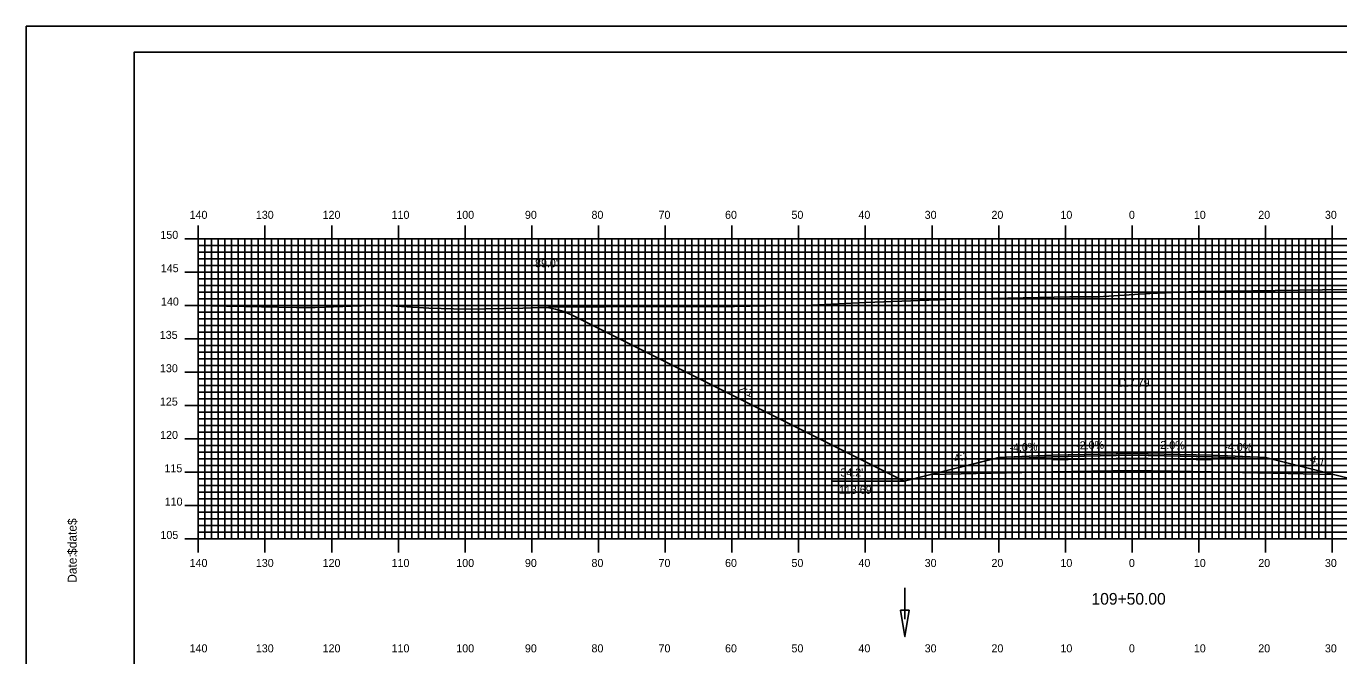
# Model space of a CAD drawing. Extents: x 1768874 to 1769217, y 442591 to 442811.
# Drawn here: x 1768874.2 to 1769071, y 442716.2 to 442810.5 of the extents above; entities that cross this region are included whole.
import ezdxf

# ---------------------------------------------------------------- set-up
doc = ezdxf.new("R2010")
doc.units = 0
for name, color, linetype in [('ANNOTATION', 7, 'Continuous'), ('BORDER', 7, 'Continuous'), ('D_Drainage_Ditch_Line', 7, 'Continuous'), ('D_Roadway_Centerline', 7, 'Continuous'), ('D_Roadway_Centerline_Text', 7, 'Continuous'), ('D_Roadway_Edge_Shoulder', 7, 'Continuous'), ('D_Roadway_Edge_TW', 7, 'Continuous'), ('D_Roadway_Pavement', 7, 'Continuous'), ('D_Roadway_SlopeLines', 7, 'Continuous'), ('D_Roadway_SubGrade', 7, 'Continuous'), ('D_Text_Standard', 7, 'Continuous'), ('H_V ANNOTATION', 7, 'Continuous'), ('MAJOR', 7, 'Continuous'), ('MINOR', 7, 'Continuous'), ('PDRAIN', 7, 'Continuous'), ('PLOT BOUNDARY', 7, 'Continuous'), ('S_Roadway_Centerline', 7, 'Continuous')]:
    doc.layers.add(name, color=color, linetype=linetype)

msp = doc.modelspace()

# ---------------------------------------------------------------- linework, layer by layer
at = {"layer": 'BORDER'}
msp.add_lwpolyline([(1768890.39, 442596.67), (1769210.39, 442596.67), (1769210.39, 442806.67), (1768890.39, 442806.67)], close=True, dxfattribs=at)
at = {"layer": 'D_Drainage_Ditch_Line'}
msp.add_line((1769005.93, 442721.66), (1769005.93, 442726.36), dxfattribs=at)
msp.add_lwpolyline([(1769006.58, 442722.97), (1769005.27, 442722.97), (1769005.93, 442719.03)], close=True, dxfattribs=at)
at = {"layer": 'D_Roadway_Centerline'}
msp.add_lwpolyline([(1768951.04, 442768.39), (1768952.29, 442768.36), (1768953.07, 442768.23), (1768953.54, 442768.15), (1768954.44, 442767.89), (1768954.79, 442767.78), (1768954.96, 442767.71), (1768956.04, 442767.24), (1769005.81, 442742.35), (1769005.81, 442742.35), (1769009.81, 442743.35), (1769009.82, 442743.35), (1769017.86, 442745.36), (1769019.99, 442745.9), (1769027.99, 442746.22), (1769030.45, 442746.27), (1769039.99, 442746.46), (1769051.99, 442746.22), (1769059.99, 442745.9), (1769070.16, 442743.35), (1769074.16, 442742.35)], dxfattribs=at)
at = {"layer": 'D_Roadway_Edge_Shoulder'}
for points in [[(1769027.99, 442746.22), (1769019.99, 442745.9), (1769019.99, 442745.65), (1769027.99, 442745.97)], [(1769051.99, 442746.22), (1769059.99, 442745.9), (1769059.99, 442745.65), (1769051.99, 442745.97)]]:
    msp.add_lwpolyline(points, close=True, dxfattribs=at)
at = {"layer": 'D_Roadway_Edge_TW'}
msp.add_lwpolyline([(1769027.99, 442745.97), (1769027.99, 442746.22), (1769039.99, 442746.46), (1769051.99, 442746.22), (1769051.99, 442745.97), (1769039.99, 442746.21)], close=True, dxfattribs=at)
at = {"layer": 'D_Roadway_Pavement'}
msp.add_lwpolyline([(1769027.99, 442745.55), (1769027.99, 442745.97), (1769039.99, 442746.21), (1769051.99, 442745.97), (1769051.99, 442745.55), (1769039.99, 442745.79)], close=True, dxfattribs=at)
at = {"layer": 'D_Roadway_SlopeLines'}
for points in [[(1769005.81, 442742.35), (1768956.04, 442767.24), (1768954.79, 442767.78), (1768953.54, 442768.15), (1768952.29, 442768.36), (1768951.04, 442768.39)], [(1769019.99, 442745.9), (1769005.81, 442742.35)], [(1769059.99, 442745.9), (1769074.16, 442742.35)]]:
    msp.add_lwpolyline(points, dxfattribs=at)
at = {"layer": 'D_Roadway_SubGrade'}
msp.add_lwpolyline([(1769027.99, 442743.72), (1769009.81, 442743.35), (1769019.99, 442745.9), (1769019.99, 442745.65), (1769027.99, 442745.97), (1769039.99, 442746.21), (1769051.99, 442745.97), (1769059.99, 442745.65), (1769059.99, 442745.9), (1769070.16, 442743.35), (1769051.99, 442743.72), (1769039.99, 442743.96)], close=True, dxfattribs=at)
at = {"layer": 'MAJOR'}
for p, q in [((1768899.99, 442780.67), (1768899.99, 442778.67)), ((1768909.99, 442780.67), (1768909.99, 442778.67)), ((1768919.99, 442780.67), (1768919.99, 442778.67)), ((1768929.99, 442780.67), (1768929.99, 442778.67)), ((1768939.99, 442780.67), (1768939.99, 442778.67)), ((1768949.99, 442780.67), (1768949.99, 442778.67)), ((1768959.99, 442780.67), (1768959.99, 442778.67)), ((1768969.99, 442780.67), (1768969.99, 442778.67)), ((1768979.99, 442780.67), (1768979.99, 442778.67)), ((1768989.99, 442780.67), (1768989.99, 442778.67)), ((1768999.99, 442780.67), (1768999.99, 442778.67)), ((1769009.99, 442780.67), (1769009.99, 442778.67)), ((1769019.99, 442780.67), (1769019.99, 442778.67)), ((1769029.99, 442780.67), (1769029.99, 442778.67)), ((1769039.99, 442780.67), (1769039.99, 442778.67)), ((1769049.99, 442780.67), (1769049.99, 442778.67)), ((1769059.99, 442780.67), (1769059.99, 442778.67)), ((1769069.99, 442780.67), (1769069.99, 442778.67)), ((1768897.98, 442778.67), (1768899.99, 442778.67)), ((1768899.99, 442778.67), (1769179.99, 442778.67)), ((1768899.99, 442733.67), (1768899.99, 442778.67)), ((1768899.99, 442733.67), (1768899.99, 442778.67)), ((1768899.99, 442778.67), (1769179.99, 442778.67)), ((1768909.99, 442733.67), (1768909.99, 442778.67)), ((1768919.99, 442733.67), (1768919.99, 442778.67)), ((1768929.99, 442733.67), (1768929.99, 442778.67)), ((1768939.99, 442733.67), (1768939.99, 442778.67)), ((1768949.99, 442733.67), (1768949.99, 442778.67)), ((1768959.99, 442733.67), (1768959.99, 442778.67)), ((1768969.99, 442733.67), (1768969.99, 442778.67)), ((1768979.99, 442733.67), (1768979.99, 442778.67)), ((1768989.99, 442733.67), (1768989.99, 442778.67)), ((1768999.99, 442733.67), (1768999.99, 442778.67)), ((1769009.99, 442733.67), (1769009.99, 442778.67)), ((1769019.99, 442733.67), (1769019.99, 442778.67)), ((1769029.99, 442733.67), (1769029.99, 442778.67)), ((1769039.99, 442733.67), (1769039.99, 442778.67)), ((1769049.99, 442733.67), (1769049.99, 442778.67)), ((1769059.99, 442733.67), (1769059.99, 442778.67)), ((1769069.99, 442733.67), (1769069.99, 442778.67)), ((1768897.98, 442773.67), (1768899.99, 442773.67)), ((1768899.99, 442773.67), (1769179.99, 442773.67)), ((1768897.98, 442768.67), (1768899.99, 442768.67)), ((1768899.99, 442768.67), (1769179.99, 442768.67)), ((1768897.98, 442763.67), (1768899.99, 442763.67)), ((1768899.99, 442763.67), (1769179.99, 442763.67)), ((1768897.98, 442758.67), (1768899.99, 442758.67)), ((1768899.99, 442758.67), (1769179.99, 442758.67)), ((1768897.98, 442753.67), (1768899.99, 442753.67)), ((1768899.99, 442753.67), (1769179.99, 442753.67)), ((1768897.98, 442748.67), (1768899.99, 442748.67)), ((1768899.99, 442748.67), (1769179.99, 442748.67)), ((1768897.98, 442743.67), (1768899.99, 442743.67)), ((1768899.99, 442743.67), (1769179.99, 442743.67)), ((1768897.98, 442738.67), (1768899.99, 442738.67)), ((1768899.99, 442738.67), (1769179.99, 442738.67)), ((1768897.98, 442733.67), (1768899.99, 442733.67)), ((1768899.99, 442733.67), (1769179.99, 442733.67)), ((1768899.99, 442733.67), (1769179.99, 442733.67)), ((1768899.99, 442731.66), (1768899.99, 442733.67)), ((1768909.99, 442731.66), (1768909.99, 442733.67)), ((1768919.99, 442731.66), (1768919.99, 442733.67)), ((1768929.99, 442731.66), (1768929.99, 442733.67)), ((1768939.99, 442731.66), (1768939.99, 442733.67)), ((1768949.99, 442731.66), (1768949.99, 442733.67)), ((1768959.99, 442731.66), (1768959.99, 442733.67)), ((1768969.99, 442731.66), (1768969.99, 442733.67)), ((1768979.99, 442731.66), (1768979.99, 442733.67)), ((1768989.99, 442731.66), (1768989.99, 442733.67)), ((1768999.99, 442731.66), (1768999.99, 442733.67)), ((1769009.99, 442731.66), (1769009.99, 442733.67)), ((1769019.99, 442731.66), (1769019.99, 442733.67)), ((1769029.99, 442731.66), (1769029.99, 442733.67)), ((1769039.99, 442731.66), (1769039.99, 442733.67)), ((1769049.99, 442731.66), (1769049.99, 442733.67)), ((1769059.99, 442731.66), (1769059.99, 442733.67)), ((1769069.99, 442731.66), (1769069.99, 442733.67))]:
    msp.add_line(p, q, dxfattribs=at)
at = {"layer": 'MINOR'}
for p, q in [((1768900.99, 442733.67), (1768900.99, 442778.67)), ((1768901.99, 442733.67), (1768901.99, 442778.67)), ((1768902.99, 442733.67), (1768902.99, 442778.67)), ((1768903.99, 442733.67), (1768903.99, 442778.67)), ((1768904.99, 442733.67), (1768904.99, 442778.67)), ((1768905.99, 442733.67), (1768905.99, 442778.67)), ((1768906.99, 442733.67), (1768906.99, 442778.67)), ((1768907.99, 442733.67), (1768907.99, 442778.67)), ((1768908.99, 442733.67), (1768908.99, 442778.67)), ((1768910.99, 442733.67), (1768910.99, 442778.67)), ((1768911.99, 442733.67), (1768911.99, 442778.67)), ((1768912.99, 442733.67), (1768912.99, 442778.67)), ((1768913.99, 442733.67), (1768913.99, 442778.67)), ((1768914.99, 442733.67), (1768914.99, 442778.67)), ((1768915.99, 442733.67), (1768915.99, 442778.67)), ((1768916.99, 442733.67), (1768916.99, 442778.67)), ((1768917.99, 442733.67), (1768917.99, 442778.67)), ((1768918.99, 442733.67), (1768918.99, 442778.67)), ((1768920.99, 442733.67), (1768920.99, 442778.67)), ((1768921.99, 442733.67), (1768921.99, 442778.67)), ((1768922.99, 442733.67), (1768922.99, 442778.67)), ((1768923.99, 442733.67), (1768923.99, 442778.67)), ((1768924.99, 442733.67), (1768924.99, 442778.67)), ((1768925.99, 442733.67), (1768925.99, 442778.67)), ((1768926.99, 442733.67), (1768926.99, 442778.67)), ((1768927.99, 442733.67), (1768927.99, 442778.67)), ((1768928.99, 442733.67), (1768928.99, 442778.67)), ((1768930.99, 442733.67), (1768930.99, 442778.67)), ((1768931.99, 442733.67), (1768931.99, 442778.67)), ((1768932.99, 442733.67), (1768932.99, 442778.67)), ((1768933.99, 442733.67), (1768933.99, 442778.67)), ((1768934.99, 442733.67), (1768934.99, 442778.67)), ((1768935.99, 442733.67), (1768935.99, 442778.67)), ((1768936.99, 442733.67), (1768936.99, 442778.67)), ((1768937.99, 442733.67), (1768937.99, 442778.67)), ((1768938.99, 442733.67), (1768938.99, 442778.67)), ((1768940.99, 442733.67), (1768940.99, 442778.67)), ((1768941.99, 442733.67), (1768941.99, 442778.67)), ((1768942.99, 442733.67), (1768942.99, 442778.67)), ((1768943.99, 442733.67), (1768943.99, 442778.67)), ((1768944.99, 442733.67), (1768944.99, 442778.67)), ((1768945.99, 442733.67), (1768945.99, 442778.67)), ((1768946.99, 442733.67), (1768946.99, 442778.67)), ((1768947.99, 442733.67), (1768947.99, 442778.67)), ((1768948.99, 442733.67), (1768948.99, 442778.67)), ((1768950.99, 442733.67), (1768950.99, 442778.67)), ((1768951.99, 442733.67), (1768951.99, 442778.67)), ((1768952.99, 442733.67), (1768952.99, 442778.67)), ((1768953.99, 442733.67), (1768953.99, 442778.67)), ((1768954.99, 442733.67), (1768954.99, 442778.67)), ((1768955.99, 442733.67), (1768955.99, 442778.67)), ((1768956.99, 442733.67), (1768956.99, 442778.67)), ((1768957.99, 442733.67), (1768957.99, 442778.67)), ((1768958.99, 442733.67), (1768958.99, 442778.67)), ((1768960.99, 442733.67), (1768960.99, 442778.67)), ((1768961.99, 442733.67), (1768961.99, 442778.67)), ((1768962.99, 442733.67), (1768962.99, 442778.67)), ((1768963.99, 442733.67), (1768963.99, 442778.67)), ((1768964.99, 442733.67), (1768964.99, 442778.67)), ((1768965.99, 442733.67), (1768965.99, 442778.67)), ((1768966.99, 442733.67), (1768966.99, 442778.67)), ((1768967.99, 442733.67), (1768967.99, 442778.67)), ((1768968.99, 442733.67), (1768968.99, 442778.67)), ((1768970.99, 442733.67), (1768970.99, 442778.67)), ((1768971.99, 442733.67), (1768971.99, 442778.67)), ((1768972.99, 442733.67), (1768972.99, 442778.67)), ((1768973.99, 442733.67), (1768973.99, 442778.67)), ((1768974.99, 442733.67), (1768974.99, 442778.67)), ((1768975.99, 442733.67), (1768975.99, 442778.67)), ((1768976.99, 442733.67), (1768976.99, 442778.67)), ((1768977.99, 442733.67), (1768977.99, 442778.67)), ((1768978.99, 442733.67), (1768978.99, 442778.67)), ((1768980.99, 442733.67), (1768980.99, 442778.67)), ((1768981.99, 442733.67), (1768981.99, 442778.67)), ((1768982.99, 442733.67), (1768982.99, 442778.67)), ((1768983.99, 442733.67), (1768983.99, 442778.67)), ((1768984.99, 442733.67), (1768984.99, 442778.67)), ((1768985.99, 442733.67), (1768985.99, 442778.67)), ((1768986.99, 442733.67), (1768986.99, 442778.67)), ((1768987.99, 442733.67), (1768987.99, 442778.67)), ((1768988.99, 442733.67), (1768988.99, 442778.67)), ((1768990.99, 442733.67), (1768990.99, 442778.67)), ((1768991.99, 442733.67), (1768991.99, 442778.67)), ((1768992.99, 442733.67), (1768992.99, 442778.67)), ((1768993.99, 442733.67), (1768993.99, 442778.67)), ((1768994.99, 442733.67), (1768994.99, 442778.67)), ((1768995.99, 442733.67), (1768995.99, 442778.67)), ((1768996.99, 442733.67), (1768996.99, 442778.67)), ((1768997.99, 442733.67), (1768997.99, 442778.67)), ((1768998.99, 442733.67), (1768998.99, 442778.67)), ((1769000.99, 442733.67), (1769000.99, 442778.67)), ((1769001.99, 442733.67), (1769001.99, 442778.67)), ((1769002.99, 442733.67), (1769002.99, 442778.67)), ((1769003.99, 442733.67), (1769003.99, 442778.67)), ((1769004.99, 442733.67), (1769004.99, 442778.67)), ((1769005.99, 442733.67), (1769005.99, 442778.67)), ((1769006.99, 442733.67), (1769006.99, 442778.67)), ((1769007.99, 442733.67), (1769007.99, 442778.67)), ((1769008.99, 442733.67), (1769008.99, 442778.67)), ((1769010.99, 442733.67), (1769010.99, 442778.67)), ((1769011.99, 442733.67), (1769011.99, 442778.67)), ((1769012.99, 442733.67), (1769012.99, 442778.67)), ((1769013.99, 442733.67), (1769013.99, 442778.67)), ((1769014.99, 442733.67), (1769014.99, 442778.67)), ((1769015.99, 442733.67), (1769015.99, 442778.67)), ((1769016.99, 442733.67), (1769016.99, 442778.67)), ((1769017.99, 442733.67), (1769017.99, 442778.67)), ((1769018.99, 442733.67), (1769018.99, 442778.67)), ((1769020.99, 442733.67), (1769020.99, 442778.67)), ((1769021.99, 442733.67), (1769021.99, 442778.67)), ((1769022.99, 442733.67), (1769022.99, 442778.67)), ((1769023.99, 442733.67), (1769023.99, 442778.67)), ((1769024.99, 442733.67), (1769024.99, 442778.67)), ((1769025.99, 442733.67), (1769025.99, 442778.67)), ((1769026.99, 442733.67), (1769026.99, 442778.67)), ((1769027.99, 442733.67), (1769027.99, 442778.67)), ((1769028.99, 442733.67), (1769028.99, 442778.67)), ((1769030.99, 442733.67), (1769030.99, 442778.67)), ((1769031.99, 442733.67), (1769031.99, 442778.67)), ((1769032.99, 442733.67), (1769032.99, 442778.67)), ((1769033.99, 442733.67), (1769033.99, 442778.67)), ((1769034.99, 442733.67), (1769034.99, 442778.67)), ((1769035.99, 442733.67), (1769035.99, 442778.67)), ((1769036.99, 442733.67), (1769036.99, 442778.67)), ((1769037.99, 442733.67), (1769037.99, 442778.67)), ((1769038.99, 442733.67), (1769038.99, 442778.67)), ((1769040.99, 442733.67), (1769040.99, 442778.67)), ((1769041.99, 442733.67), (1769041.99, 442778.67)), ((1769042.99, 442733.67), (1769042.99, 442778.67)), ((1769043.99, 442733.67), (1769043.99, 442778.67)), ((1769044.99, 442733.67), (1769044.99, 442778.67)), ((1769045.99, 442733.67), (1769045.99, 442778.67)), ((1769046.99, 442733.67), (1769046.99, 442778.67)), ((1769047.99, 442733.67), (1769047.99, 442778.67)), ((1769048.99, 442733.67), (1769048.99, 442778.67)), ((1769050.99, 442733.67), (1769050.99, 442778.67)), ((1769051.99, 442733.67), (1769051.99, 442778.67)), ((1769052.99, 442733.67), (1769052.99, 442778.67)), ((1769053.99, 442733.67), (1769053.99, 442778.67)), ((1769054.99, 442733.67), (1769054.99, 442778.67)), ((1769055.99, 442733.67), (1769055.99, 442778.67)), ((1769056.99, 442733.67), (1769056.99, 442778.67)), ((1769057.99, 442733.67), (1769057.99, 442778.67)), ((1769058.99, 442733.67), (1769058.99, 442778.67)), ((1769060.99, 442733.67), (1769060.99, 442778.67)), ((1769061.99, 442733.67), (1769061.99, 442778.67)), ((1769062.99, 442733.67), (1769062.99, 442778.67)), ((1769063.99, 442733.67), (1769063.99, 442778.67)), ((1769064.99, 442733.67), (1769064.99, 442778.67)), ((1769065.99, 442733.67), (1769065.99, 442778.67)), ((1769066.99, 442733.67), (1769066.99, 442778.67)), ((1769067.99, 442733.67), (1769067.99, 442778.67)), ((1769068.99, 442733.67), (1769068.99, 442778.67)), ((1768899.99, 442777.67), (1769179.99, 442777.67)), ((1768899.99, 442777.67), (1768901.99, 442777.67)), ((1768899.99, 442776.67), (1769179.99, 442776.67)), ((1768899.99, 442776.67), (1768901.99, 442776.67)), ((1768899.99, 442775.67), (1769179.99, 442775.67)), ((1768899.99, 442775.67), (1768901.99, 442775.67)), ((1768899.99, 442774.67), (1769179.99, 442774.67)), ((1768899.99, 442774.67), (1768901.99, 442774.67)), ((1768899.99, 442772.67), (1769179.99, 442772.67)), ((1768899.99, 442772.67), (1768901.99, 442772.67)), ((1768899.99, 442771.67), (1769179.99, 442771.67)), ((1768899.99, 442771.67), (1768901.99, 442771.67)), ((1768899.99, 442770.67), (1769179.99, 442770.67)), ((1768899.99, 442770.67), (1768901.99, 442770.67)), ((1768899.99, 442769.67), (1769179.99, 442769.67)), ((1768899.99, 442769.67), (1768901.99, 442769.67)), ((1768899.99, 442767.67), (1769179.99, 442767.67)), ((1768899.99, 442767.67), (1768901.99, 442767.67)), ((1768899.99, 442766.67), (1769179.99, 442766.67)), ((1768899.99, 442766.67), (1768901.99, 442766.67)), ((1768899.99, 442765.67), (1769179.99, 442765.67)), ((1768899.99, 442765.67), (1768901.99, 442765.67)), ((1768899.99, 442764.67), (1769179.99, 442764.67)), ((1768899.99, 442764.67), (1768901.99, 442764.67)), ((1768899.99, 442762.67), (1769179.99, 442762.67)), ((1768899.99, 442762.67), (1768901.99, 442762.67)), ((1768899.99, 442761.67), (1769179.99, 442761.67)), ((1768899.99, 442761.67), (1768901.99, 442761.67)), ((1768899.99, 442760.67), (1769179.99, 442760.67)), ((1768899.99, 442760.67), (1768901.99, 442760.67)), ((1768899.99, 442759.67), (1769179.99, 442759.67)), ((1768899.99, 442759.67), (1768901.99, 442759.67)), ((1768899.99, 442757.67), (1769179.99, 442757.67)), ((1768899.99, 442757.67), (1768901.99, 442757.67)), ((1768899.99, 442756.67), (1769179.99, 442756.67)), ((1768899.99, 442756.67), (1768901.99, 442756.67)), ((1768899.99, 442755.67), (1769179.99, 442755.67)), ((1768899.99, 442755.67), (1768901.99, 442755.67)), ((1768899.99, 442754.67), (1769179.99, 442754.67)), ((1768899.99, 442754.67), (1768901.99, 442754.67)), ((1768899.99, 442752.67), (1769179.99, 442752.67)), ((1768899.99, 442752.67), (1768901.99, 442752.67)), ((1768899.99, 442751.67), (1769179.99, 442751.67)), ((1768899.99, 442751.67), (1768901.99, 442751.67)), ((1768899.99, 442750.67), (1769179.99, 442750.67)), ((1768899.99, 442750.67), (1768901.99, 442750.67)), ((1768899.99, 442749.67), (1769179.99, 442749.67)), ((1768899.99, 442749.67), (1768901.99, 442749.67)), ((1768899.99, 442747.67), (1769179.99, 442747.67)), ((1768899.99, 442747.67), (1768901.99, 442747.67)), ((1768899.99, 442746.67), (1769179.99, 442746.67)), ((1768899.99, 442746.67), (1768901.99, 442746.67)), ((1768899.99, 442745.67), (1769179.99, 442745.67)), ((1768899.99, 442745.67), (1768901.99, 442745.67)), ((1768899.99, 442744.67), (1769179.99, 442744.67)), ((1768899.99, 442744.67), (1768901.99, 442744.67)), ((1768899.99, 442742.67), (1769179.99, 442742.67)), ((1768899.99, 442742.67), (1768901.99, 442742.67)), ((1768899.99, 442741.67), (1769179.99, 442741.67)), ((1768899.99, 442741.67), (1768901.99, 442741.67)), ((1768899.99, 442740.67), (1769179.99, 442740.67)), ((1768899.99, 442740.67), (1768901.99, 442740.67)), ((1768899.99, 442739.67), (1769179.99, 442739.67)), ((1768899.99, 442739.67), (1768901.99, 442739.67)), ((1768899.99, 442737.67), (1769179.99, 442737.67)), ((1768899.99, 442737.67), (1768901.99, 442737.67)), ((1768899.99, 442736.67), (1769179.99, 442736.67)), ((1768899.99, 442736.67), (1768901.99, 442736.67)), ((1768899.99, 442735.67), (1769179.99, 442735.67)), ((1768899.99, 442735.67), (1768901.99, 442735.67)), ((1768899.99, 442734.67), (1769179.99, 442734.67)), ((1768899.99, 442734.67), (1768901.99, 442734.67))]:
    msp.add_line(p, q, dxfattribs=at)
at = {"layer": 'PDRAIN'}
msp.add_line((1768995.09, 442742.35), (1769005.81, 442742.35), dxfattribs=at)
at = {"layer": 'PLOT BOUNDARY'}
msp.add_lwpolyline([(1768874.2, 442590.55), (1769214.2, 442590.55), (1769214.2, 442810.55), (1768874.2, 442810.55)], close=True, dxfattribs=at)
at = {"layer": 'S_Roadway_Centerline'}
msp.add_lwpolyline([(1768899.99, 442768.66), (1768904.24, 442768.56), (1768914.74, 442768.36), (1768917.52, 442768.39), (1768927.22, 442768.71), (1768934.57, 442768.3), (1768940.08, 442768.11), (1768948.67, 442768.3), (1768953.74, 442768.5), (1768961.04, 442768.46), (1768972.46, 442768.55), (1768980.39, 442768.53), (1768987.48, 442768.67), (1768992.09, 442768.72), (1769000.08, 442769.12), (1769010.84, 442769.54), (1769012.03, 442769.57), (1769030.64, 442769.98), (1769034.94, 442769.97), (1769042.66, 442770.48), (1769047.17, 442770.68), (1769049.78, 442770.79), (1769057.88, 442770.89), (1769068.53, 442771.04), (1769077.1, 442771.05)], dxfattribs=at)

# ---------------------------------------------------------------- texts
at = {"layer": 'ANNOTATION'}
for s, rotation, p in [('2:1', 333.4349, (1768980.86, 442755.87)), ('4:1', 14.0389, (1769013.44, 442745.12)), ('-4.0%', 2.2905, (1769021.62, 442746.76)), ('-2.0%', 1.1458, (1769031.6, 442747.09)), ('-2.0%', 358.8542, (1769043.67, 442747.18)), ('-4.0%', 357.7095, (1769053.78, 442746.95)), ('4:1', 345.9611, (1769066.58, 442745.11))]:
    msp.add_text(s, height=1.2, rotation=rotation, dxfattribs=at).set_placement(p)
for s, p in [("34.2'", (1768996.25, 442743.04)), ('113.69', (1768996.03, 442740.44))]:
    msp.add_text(s, height=1.2, dxfattribs=at).set_placement(p)
at = {"layer": 'BORDER'}
for s, p in [('$date$', (1768881.76, 442731.28)), ('Date:', (1768881.76, 442727.1))]:
    msp.add_text(s, height=1.339, rotation=90, dxfattribs=at).set_placement(p)
at = {"layer": 'D_Roadway_Centerline'}
for s, p in [('C', (1769039.98, 442746.46)), ('L', (1769039.99, 442746.45))]:
    msp.add_text(s, height=0.0146, dxfattribs=at).set_placement(p)
at = {"layer": 'D_Roadway_Centerline_Text'}
msp.add_text('117.79', height=1.2, dxfattribs=at).set_placement((1769037.7, 442756.49))
at = {"layer": 'D_Text_Standard'}
msp.add_text("89.0'", height=1.2, dxfattribs=at).set_placement((1768950.48, 442774.41))
at = {"layer": 'H_V ANNOTATION'}
for s, height, p in [('140', 1.2, (1768898.69, 442781.67)), ('130', 1.2, (1768908.62, 442781.67)), ('120', 1.2, (1768918.63, 442781.67)), ('110', 1.2, (1768928.97, 442781.67)), ('100', 1.2, (1768938.67, 442781.67)), ('90', 1.2, (1768948.96, 442781.67)), ('80', 1.2, (1768958.94, 442781.67)), ('70', 1.2, (1768968.99, 442781.67)), ('60', 1.2, (1768978.96, 442781.67)), ('50', 1.2, (1768988.92, 442781.67)), ('40', 1.2, (1768998.96, 442781.67)), ('30', 1.2, (1769008.89, 442781.67)), ('20', 1.2, (1769018.9, 442781.67)), ('10', 1.2, (1769029.24, 442781.67)), ('0', 1.2, (1769039.51, 442781.67)), ('10', 1.2, (1769049.24, 442781.67)), ('20', 1.2, (1769058.9, 442781.67)), ('30', 1.2, (1769068.89, 442781.67)), ('150', 1.2, (1768894.31, 442778.67)), ('145', 1.2, (1768894.37, 442773.67)), ('140', 1.2, (1768894.4, 442768.67)), ('135', 1.2, (1768894.22, 442763.67)), ('130', 1.2, (1768894.25, 442758.67)), ('125', 1.2, (1768894.24, 442753.67)), ('120', 1.2, (1768894.27, 442748.67)), ('115', 1.2, (1768894.92, 442743.67)), ('110', 1.2, (1768894.96, 442738.67)), ('105', 1.2, (1768894.32, 442733.67)), ('140', 1.2, (1768898.69, 442729.47)), ('130', 1.2, (1768908.62, 442729.47)), ('120', 1.2, (1768918.63, 442729.47)), ('110', 1.2, (1768928.97, 442729.47)), ('100', 1.2, (1768938.67, 442729.47)), ('90', 1.2, (1768948.96, 442729.47)), ('80', 1.2, (1768958.94, 442729.47)), ('70', 1.2, (1768968.99, 442729.47)), ('60', 1.2, (1768978.96, 442729.47)), ('50', 1.2, (1768988.92, 442729.47)), ('40', 1.2, (1768998.96, 442729.47)), ('30', 1.2, (1769008.89, 442729.47)), ('20', 1.2, (1769018.9, 442729.47)), ('10', 1.2, (1769029.24, 442729.47)), ('0', 1.2, (1769039.51, 442729.47)), ('10', 1.2, (1769049.24, 442729.47)), ('20', 1.2, (1769058.9, 442729.47)), ('30', 1.2, (1769068.89, 442729.47)), ('109+50.00', 1.75, (1769033.9, 442723.82)), ('140', 1.2, (1768898.69, 442716.67)), ('130', 1.2, (1768908.62, 442716.67)), ('120', 1.2, (1768918.63, 442716.67)), ('110', 1.2, (1768928.97, 442716.67)), ('100', 1.2, (1768938.67, 442716.67)), ('90', 1.2, (1768948.96, 442716.67)), ('80', 1.2, (1768958.94, 442716.67)), ('70', 1.2, (1768968.99, 442716.67)), ('60', 1.2, (1768978.96, 442716.67)), ('50', 1.2, (1768988.92, 442716.67)), ('40', 1.2, (1768998.96, 442716.67)), ('30', 1.2, (1769008.89, 442716.67)), ('20', 1.2, (1769018.9, 442716.67)), ('10', 1.2, (1769029.24, 442716.67)), ('0', 1.2, (1769039.51, 442716.67)), ('10', 1.2, (1769049.24, 442716.67)), ('20', 1.2, (1769058.9, 442716.67)), ('30', 1.2, (1769068.89, 442716.67))]:
    msp.add_text(s, height=height, dxfattribs=at).set_placement(p)
at = {"layer": 'MAJOR'}
msp.add_text('-', height=0.012, dxfattribs=at).set_placement((1768899.98, 442733.67))

doc.saveas('drawing.dxf')
